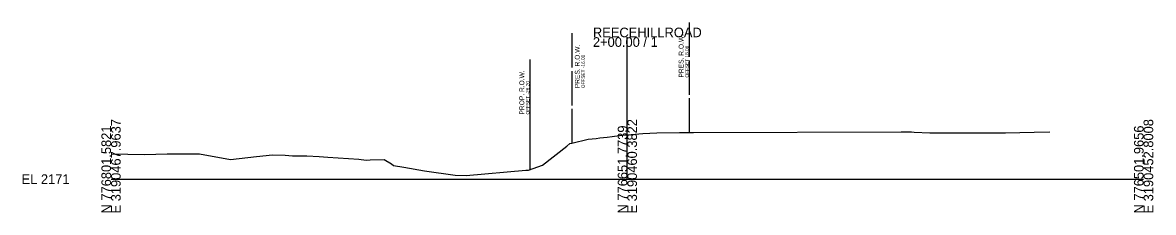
# Model space of a CAD drawing. Extents: x -26 to 303, y -25 to 5046.
# Drawn here: x -25.7 to 302.8, y 4990.3 to 5045.6 of the extents above; entities that cross this region are included whole.
import ezdxf

# ---------------------------------------------------------------- set-up
doc = ezdxf.new("R2010")
doc.units = 0
for name, color, linetype in [('DESIGN - ROW - Right-of-Way and Easement Labels', 7, 'Continuous'), ('DESIGN - ROW - Right-of-Way Linework', 7, 'Continuous'), ('DESIGN - SHEET - Light Grid', 7, 'Continuous'), ('SURVEY - GROUND - Top of Ground', 7, 'Continuous'), ('SURVEY - PROPERTY - ROW Lines', 7, 'Continuous'), ('SURVEY - PROPERTY - ROW Lines Text', 7, 'Continuous')]:
    doc.layers.add(name, color=color, linetype=linetype)

msp = doc.modelspace()

# ---------------------------------------------------------------- linework, layer by layer
at = {"layer": 'DESIGN - ROW - Right-of-Way Linework'}
msp.add_line((121.8, 5002.8), (121.8, 5034.8), dxfattribs=at)
at = {"layer": 'DESIGN - SHEET - Light Grid'}
for p, q in [((150, 5000), (150, 5041.3)), ((0, 5000), (150, 5000)), ((150, 5000), (300, 5000))]:
    msp.add_line(p, q, dxfattribs=at)
at = {"layer": 'SURVEY - GROUND - Top of Ground'}
msp.add_line((169.24, 5013.58), (229.54, 5013.77), dxfattribs=at)
for points in [[(0, 5007.34), (9.75, 5007.17), (16.34, 5007.39), (20.28, 5007.41), (25.68, 5007.36), (34.67, 5005.74), (42.23, 5006.54), (46.88, 5007.03), (50.63, 5006.97), (52.72, 5006.81), (56.9, 5006.75), (60.49, 5006.57), (63.02, 5006.44), (72.02, 5005.81), (74.17, 5005.55), (75.33, 5005.65), (79.39, 5005.76), (81.5, 5004.46), (82.02, 5003.97), (85.09, 5003.48), (91.05, 5002.4), (99.95, 5001.19), (103.13, 5001.07), (120.54, 5002.57), (121.26, 5002.61), (125.34, 5004.06), (132.44, 5009.61), (133.34, 5010.33), (133.91, 5010.43), (138.63, 5011.62), (140.91, 5011.85), (142.02, 5012), (144.15, 5012.26), (145.62, 5012.4), (148.4, 5012.75), (150, 5012.88), (154.54, 5013.26), (158.54, 5013.48), (165.14, 5013.54), (169.24, 5013.58)], [(229.54, 5013.77), (232.61, 5013.74), (233.34, 5013.71), (237.86, 5013.51), (242.99, 5013.49), (247.26, 5013.5), (259.89, 5013.47), (268.16, 5013.65), (272.78, 5013.72)]]:
    msp.add_lwpolyline(points, dxfattribs=at)
at = {"layer": 'SURVEY - PROPERTY - ROW Lines'}
for p, q in [((168.08, 5035.57), (168.08, 5045.57)), ((134, 5032.46), (134, 5042.46)), ((168.08, 5024.57), (168.08, 5034.57)), ((134, 5021.46), (134, 5031.46)), ((168.08, 5013.57), (168.08, 5023.57)), ((134, 5010.46), (134, 5020.46))]:
    msp.add_line(p, q, dxfattribs=at)

# ---------------------------------------------------------------- texts
at = {"layer": 'DESIGN - ROW - Right-of-Way and Easement Labels'}
for s, height, p in [('PROP. R.O.W.', 1.4, (120.05, 5018.8)), ('OFFSET -28.20', 1, (121.55, 5018.8))]:
    msp.add_text(s, height=height, rotation=90, dxfattribs=at).set_placement(p)
at = {"layer": 'DESIGN - SHEET - Light Grid'}
for s, p in [('REECEHILLROAD', (140, 5041.3)), ('2+00.00 / 1', (140, 5038.5)), ('EL 2171', (-26, 4998.6))]:
    msp.add_text(s, height=2.8, dxfattribs=at).set_placement(p)
for s, p in [('E 3190467.9637', (2.8, 4990)), ('E 3190460.3822', (152.8, 4990)), ('E 3190452.8008', (302.8, 4990)), ('N 776801.5821', (0, 4990)), ('N 776651.7739', (150, 4990)), ('N 776501.9656', (300, 4990))]:
    msp.add_text(s, height=2.8, rotation=90, dxfattribs=at).set_placement(p)
at = {"layer": 'SURVEY - PROPERTY - ROW Lines Text'}
for s, height, p in [('PRES. R.O.W.', 1.4, (166.33, 5029.57)), ('PRES. R.O.W.', 1.4, (136.15, 5026.46)), ('OFFSET 18.08', 1, (167.83, 5029.57)), ('OFFSET -16.00', 1, (137.65, 5026.46))]:
    msp.add_text(s, height=height, rotation=90, dxfattribs=at).set_placement(p)

doc.saveas('drawing.dxf')
